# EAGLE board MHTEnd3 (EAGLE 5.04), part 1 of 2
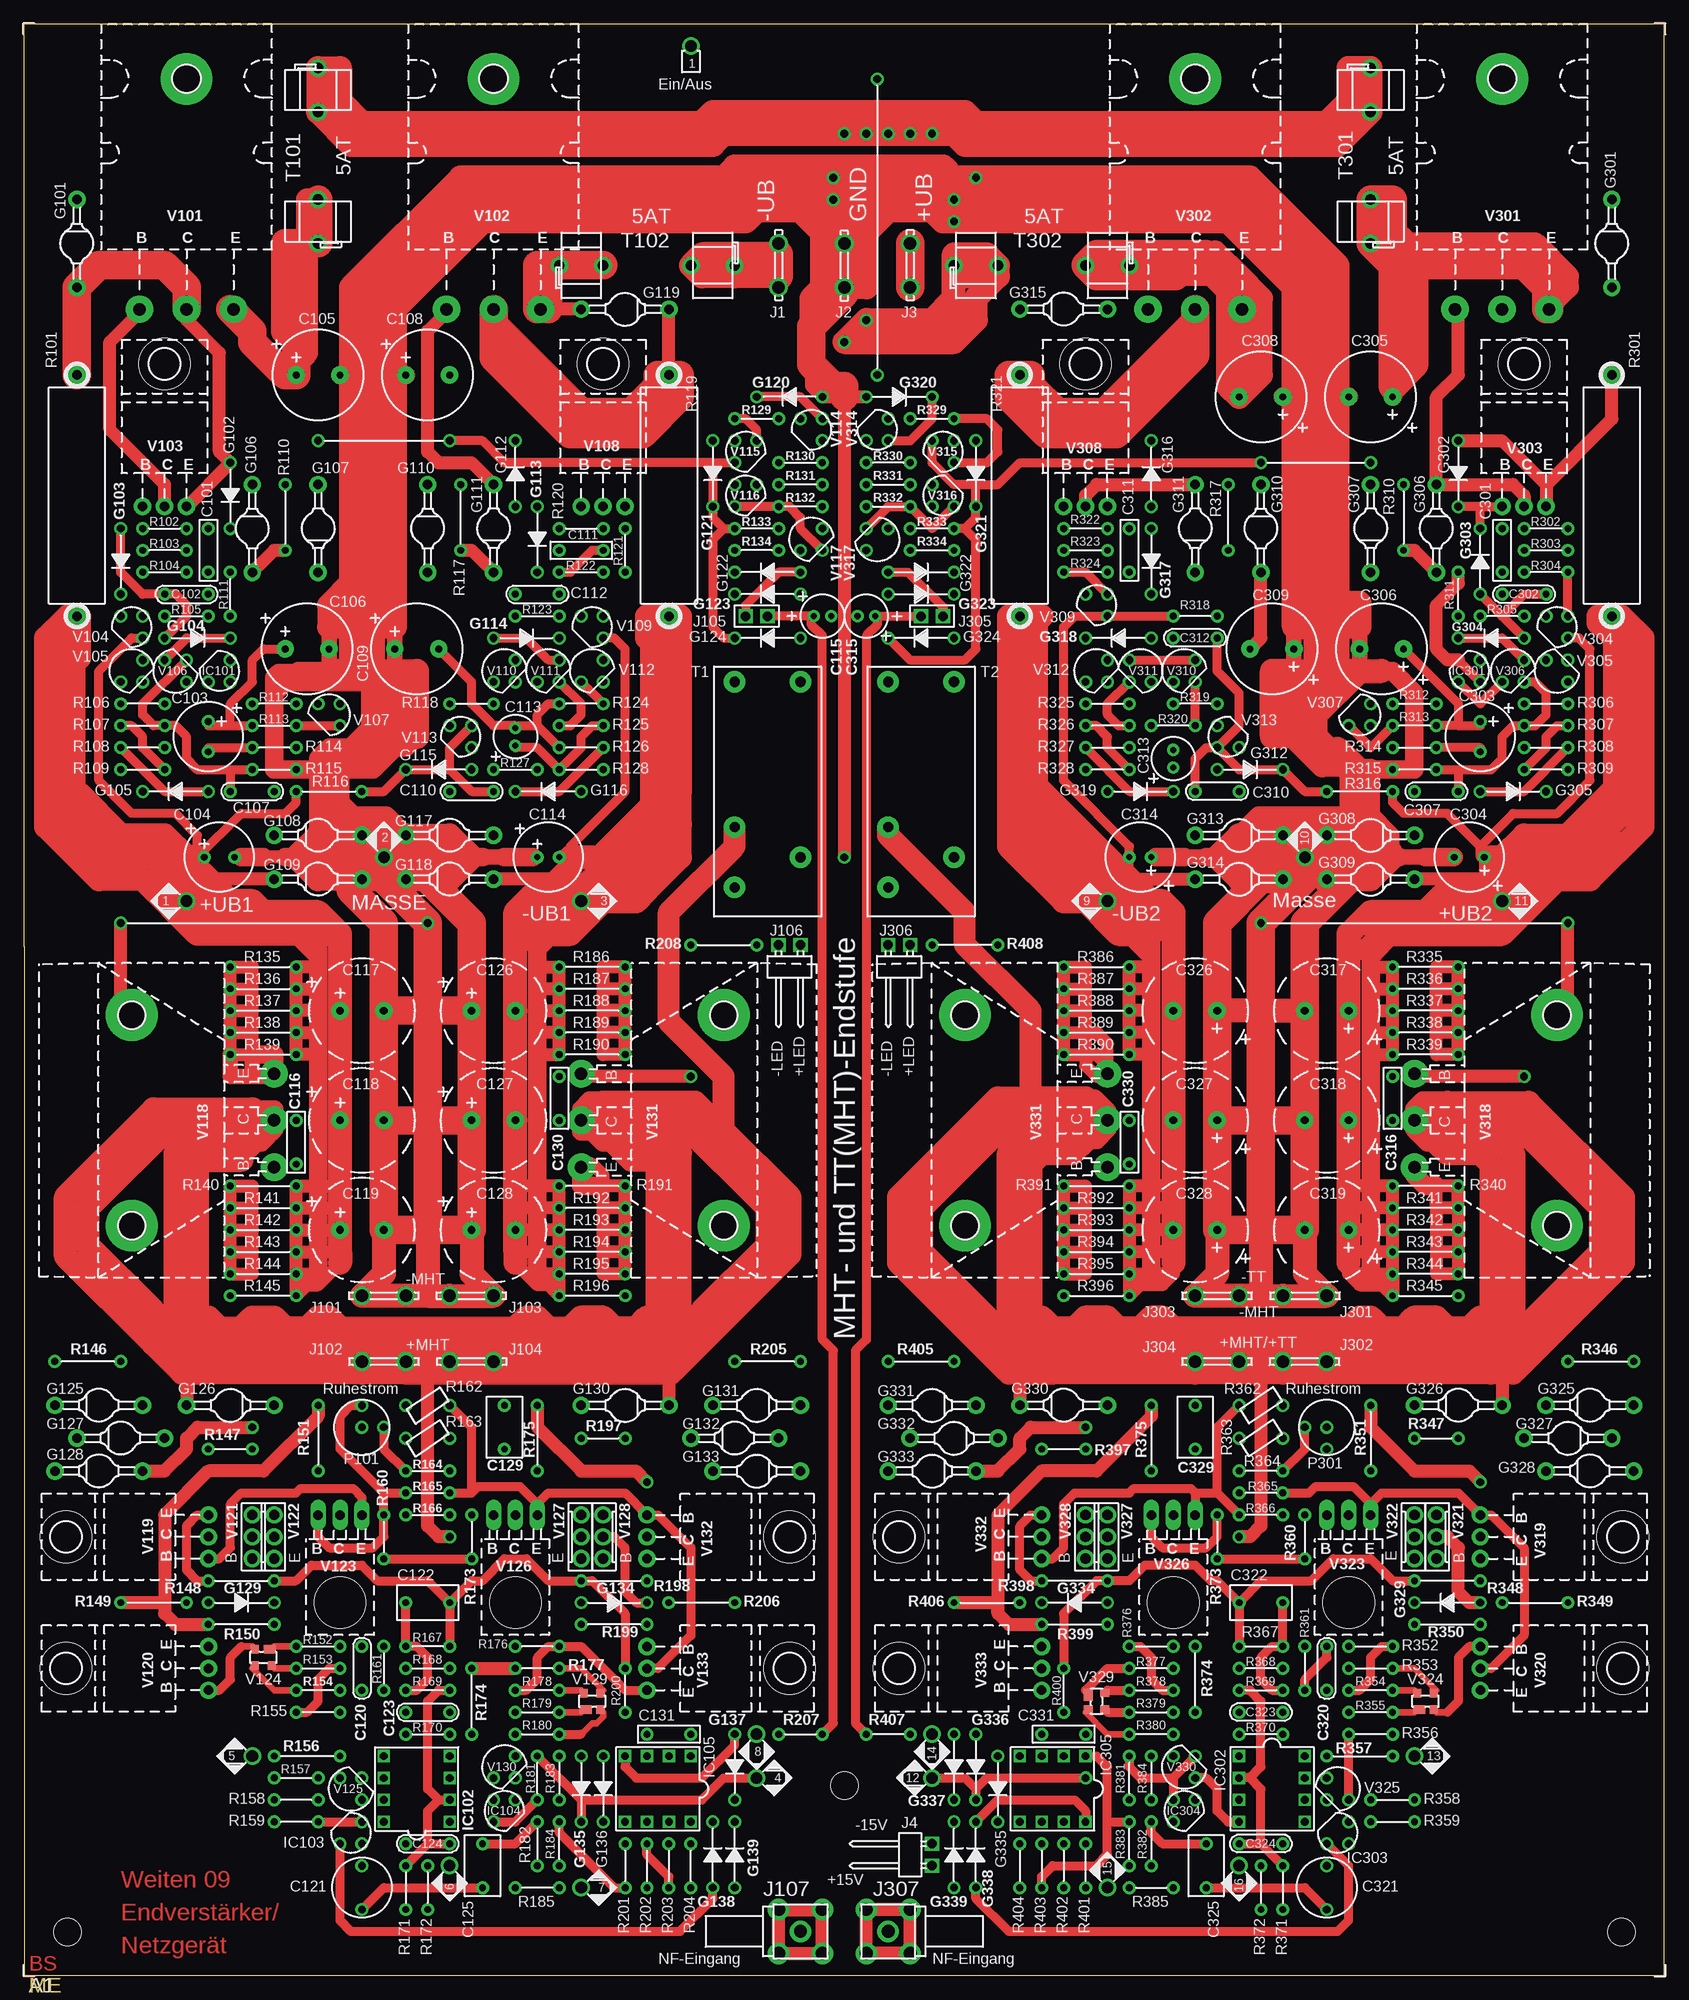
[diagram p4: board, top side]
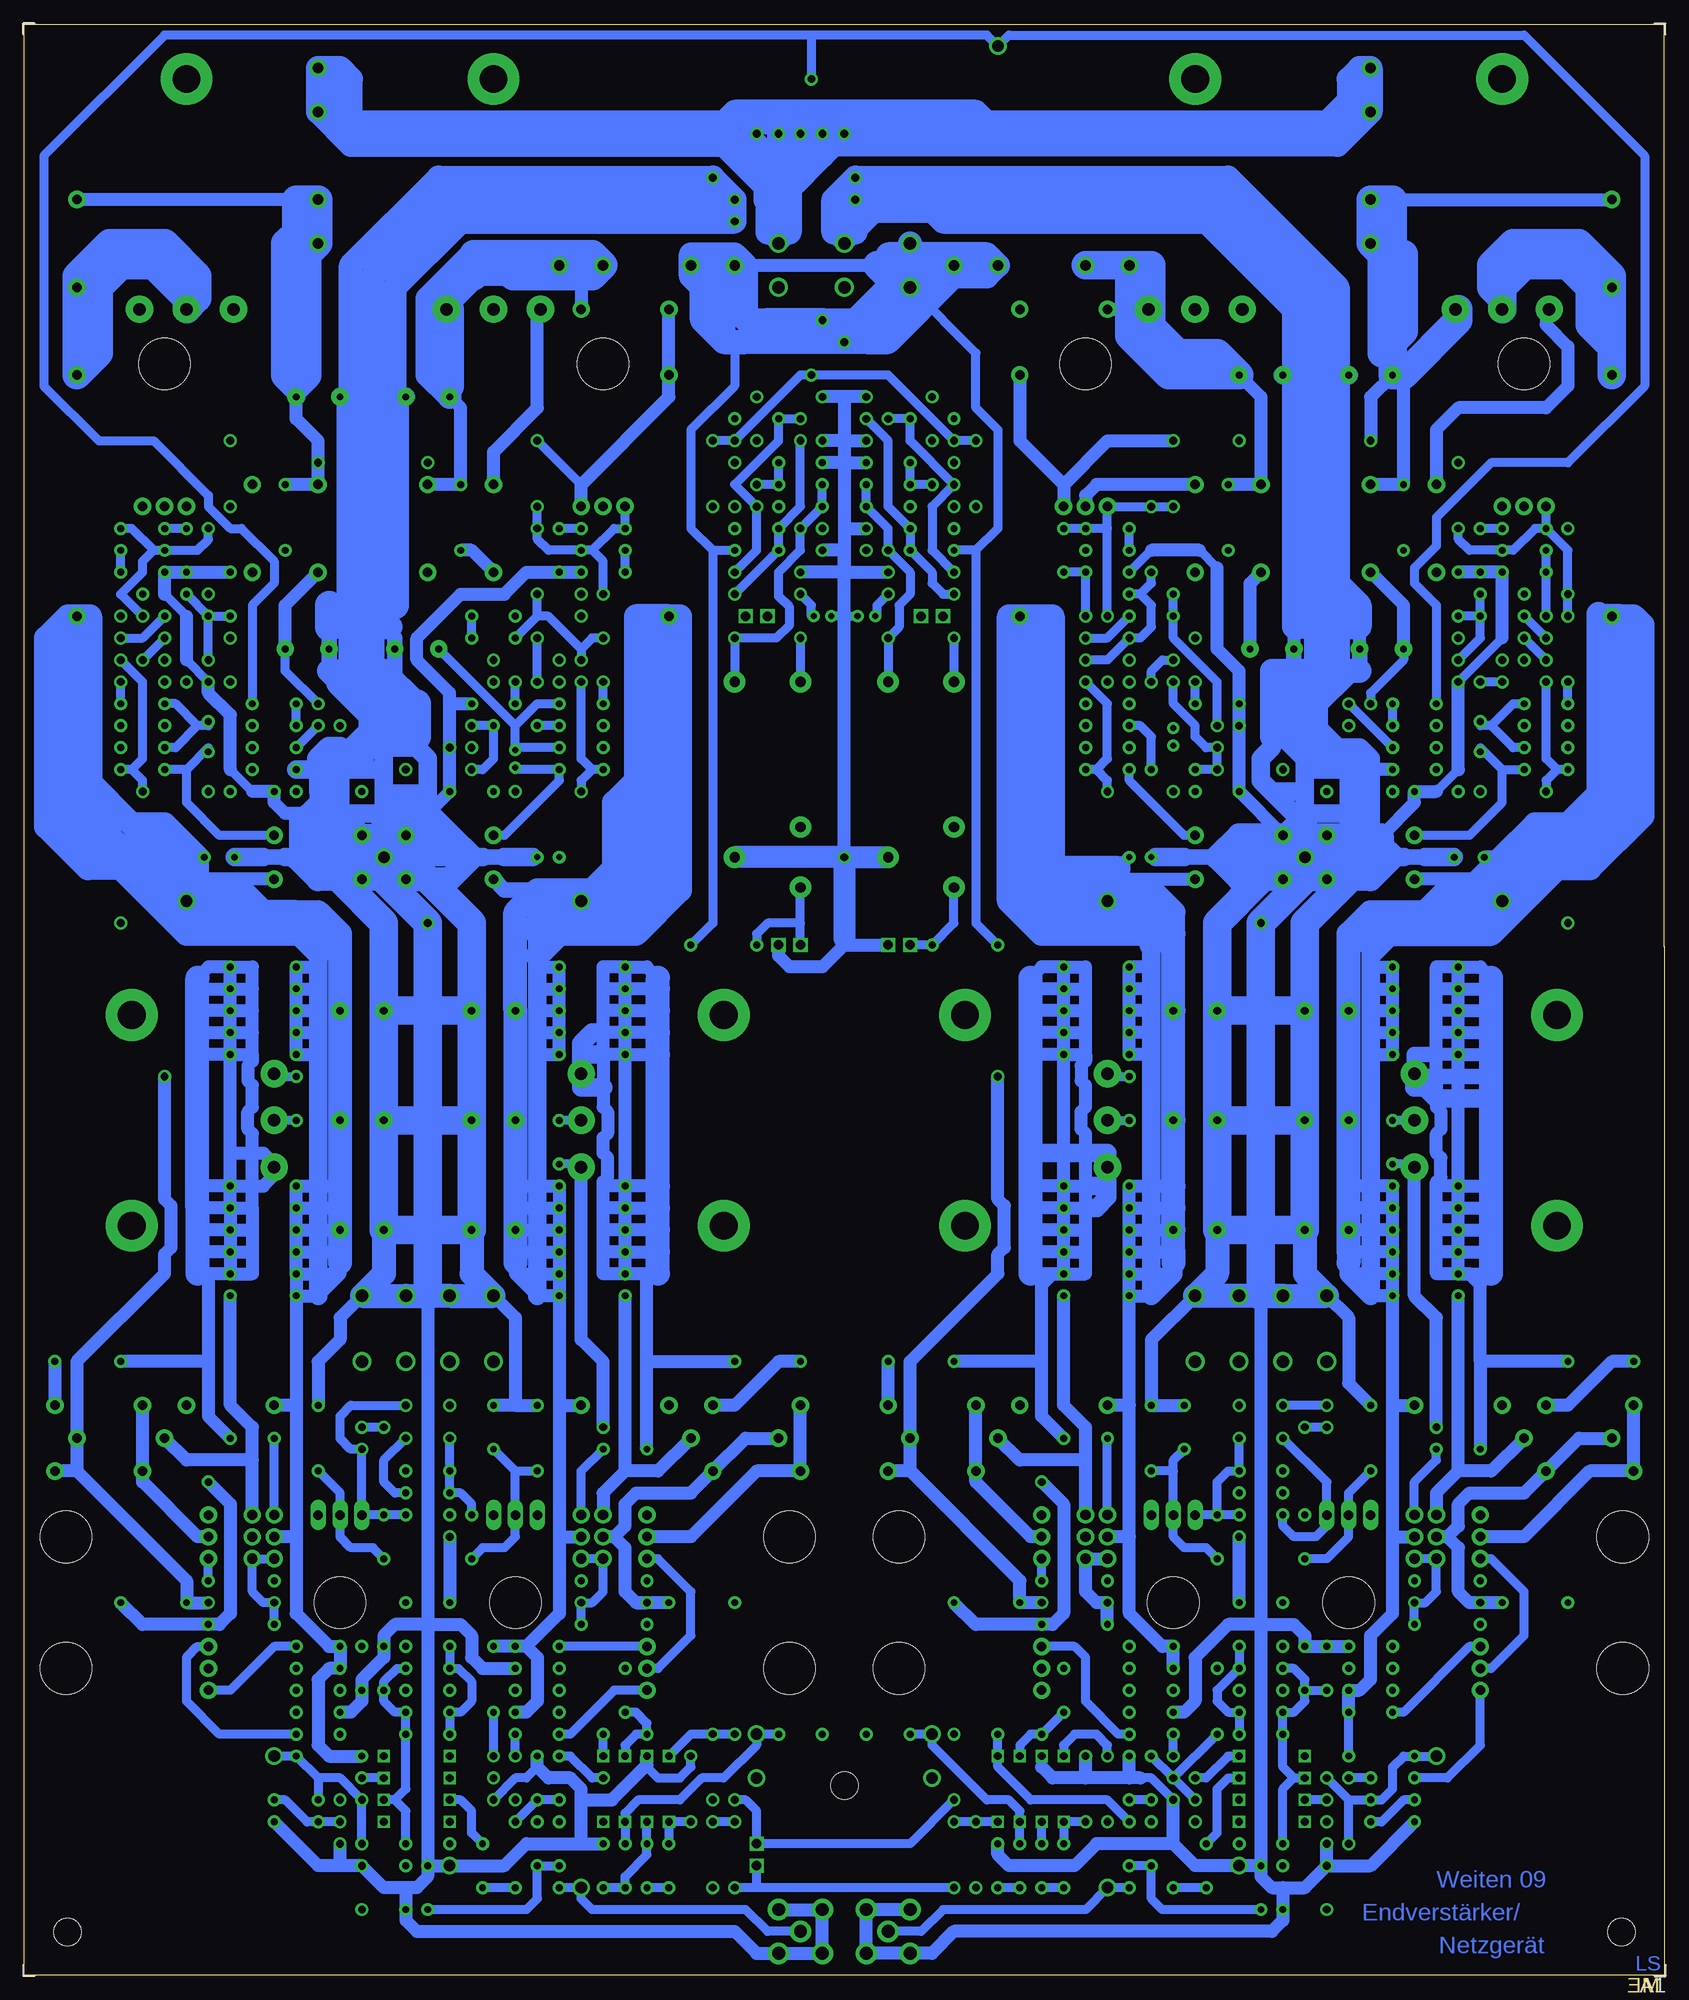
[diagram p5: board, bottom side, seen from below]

Size 190 x 226.06 mm. Coordinates in mm from the lower left corner, seen from the top.
Outline: 190,120 190,0 0,0 0,119.24
Outline: 190,119.38 190,226.06 0,226.06 0,119.13
Copper layers (1*16): Oben/V2 0.035mm / dielectric 1.5mm / Unten/V1 0.035mm
Design rules "default": minimum track width 8mil, minimum drill 24mil, track to track 20mil, track to pad 20mil, pad to pad 20mil, via to via 20mil, smd to smd 20mil, copper to edge 20mil, drill to drill 20mil, minimum pad ring 10mil, minimum via ring 8mil, stop-mask expansion 5mil, vias tented up to drill 0mil, thermal gap 10mil
Holes 6 mm at 185.17,50.8 101.35,50.8 4.83,50.8 88.65,50.8 101.35,35.56 88.65,35.56 185.17,35.56 4.83,35.56 67.06,186.69 16.26,186.69 173.74,186.69 122.94,186.69

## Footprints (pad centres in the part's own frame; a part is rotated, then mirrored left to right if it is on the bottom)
M05T2,5 = drill 0.8 pad 1.499 round: 1 -2.54,0; 2 2.54,0
K5 = drill 0.8 pad 1.499 round: 1 -2.54,0; 2 2.54,0
E3,5S08 = drill 0.8 pad 1.499 round: 1 -1.753,0; 2 1.753,0
E05S10,5 = drill 0.8 pad 2.007 round: 1 -2.54,0; 2 2.54,0
E2,0S05 = drill 0.7 pad 1.397 round: 1 -1.016,0; 2 1.016,0
E2,5S08@1 = drill 0.7 pad 1.499 round: 1 -1.27,0; 2 1.27,0
E05S12,7U = drill 0.9 pad 2.007 round: 1 -2.54,0; 2 2.54,0
KP5/7 = drill 0.9 pad 1.499 round: 1 -2.54,0; 2 2.54,0
M05T4,5 = drill 0.8 pad 1.499 round: 1 -2.54,0; 2 2.54,0
E2,5S08 = drill 0.7 pad 1.499 round: 1 -1.27,0; 2 1.27,0
SOD-57 = drill 1.1 pad 2.007 round: 1 -5.08,0; 2 5.08,0
DIO7-5 = drill 0.9 pad 1.499 round: 1 -2.54,0; 2 5.08,0
TO-92/BC = drill 0.9 pad 1.499 round: 1 1.27,1.27; 2 1.27,-1.27; 3 -1.27,-1.27
DIL-8 = drill 0.9 pad 1.397 square: 1 0,0; 2 2.54,0; 3 5.08,0; 4 7.62,0; 5 7.62,7.62; 6 5.08,7.62; 7 2.54,7.62; 8 0,7.62
FLACH6,3 = drill 1.45 pad 2.184 round: 1 -2.54,0; 2 2.54,0
BERG02SW = drill 1.1 pad 1.499 square: 1 0,0; 2 0,2.54
BERG02SG = drill 1.1 pad 1.499 square: 1 0,0; 2 2.54,0
SMBR665 = drill 1.5 pad 2.489 round: 1 0,0; 2 -2.54,2.54; 3 -2.54,-2.54; 4 2.54,-2.54; 5 2.54,2.54
MESSPU/R = drill 1.35 pad 2.007 round: 1 0,0
T82P = drill 0.9 pad 1.499 round: 1 -2.54,0; 2 0,2.54; S 0,0
R27,5 = drill 1.1 pad 2.007 round: 1 -12.7,0; 2 15.24,0
R5 = drill 0.8 pad 1.499 round: 1 -2.54,0; 2 2.54,0
R7,5 = drill 0.8 pad 1.499 round: 1 -3.81,0; 2 3.81,0
NTC5,0B = drill 0.9 pad 1.499 round: 1 -2.54,0; 2 2.54,0
TYCORT314 = drill 1.2 pad 2.489 round: 11 7.62,2.54; 12 4.12,-5.08; 14 11.12,-5.08; A1 -12.7,-5.08; A2 -12.7,2.54
SICH5*20 = drill 1.2 pad 2.032 round: 1 -10.16,0; 2 -5.08,0; 3 5.08,0; 4 10.16,0
M3 = hole 3.2: 0,0
LÖTFA = drill 1.35 pad 2.032 round: 1 0,0
TO-264/LU = drill 1.45 pad 3.175 round: 1 -5.45,0; 2 0,0; 3 5.43,0
TO-220/LU = drill 1.1 pad 2.007 round: 1 -2.54,0; 2 0,0; 3 2.54,0
TO-92 = drill 0.9 pad 1.499 round: 1 -1.27,-1.27; 2 1.27,-1.27; 3 1.27,1.27
SOT-54 = drill 0.9 pad 1.499 round: B 1.27,-1.27; C 1.27,1.27; E -1.27,1.27
MT200LU = drill 1.45 pad 3.175 round: 1 -5.41,0; 2 0,0; 3 5.41,0
TO-126/S = drill 1.2 pad 2.007 round: 1 -2.54,0; 2 0,0; 3 2.54,0
TO-126/LU = drill 1.1 pad 1.778 long: 1 -2.54,0; 2 0,0; 3 2.54,0 | hole 6: 0,10.16
SOT143 = smd 1.397 x 1.016: 1 0.737,0.965 | smd 0.94 x 1.016: 2 -0.965,0.965; 3 -0.965,-0.94; 4 0.965,-0.94

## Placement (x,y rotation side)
C101  22n/100  [M05T2,5]  21.34,165.1 270 top
C102  12p  [K5]  18.8,160.02 0 top
C103  220µ/25  [E3,5S08]  21.34,143.51 270 top
C104  47µ/63  [E3,5S08]  22.61,129.54 0 top
C105  100µ/63  [E05S10,5]  34.04,185.42 0 top
C106  100µ/63  [E05S10,5]  32.77,153.67 0 top
C107  10n/100  [K5]  26.42,137.16 0 top
C108  100µ/63  [E05S10,5]  46.74,185.42 0 top
C109  100µ/63  [E05S10,5]  45.47,153.67 0 top
C110  1,5n  [K5]  51.82,137.16 0 top
C111  10n/100  [M05T2,5]  64.52,165.1 180 top
C112  12p  [K5]  59.44,160.02 0 top
C113  10µ/100  [E2,0S05]  56.9,143.51 90 top
C114  47µ/63  [E2,5S08@1]  60.71,129.54 0 top
C115  10µ/100  [E2,0S05]  92.46,157.48 0 top
C116  0p  [M05T2,5]  31.5,96.52 90 top
C117  470µ/63  [E05S12,7U]  39.12,111.76 0 top
C118  470µ/63  [E05S12,7U]  39.12,99.06 0 top
C119  470µ/63  [E05S12,7U]  39.12,86.36 0 top
C120  1,5n  [K5]  39.12,35.56 270 top
C121  270p  [KP5/7]  39.12,10.16 90 top
C122  33n/100  [M05T4,5]  46.74,43.18 180 top
C123  82p  [K5]  46.74,30.48 0 top
C124  27p  [K5]  46.74,15.24 0 top
C125  22n/100  [M05T4,5]  53.09,12.7 90 top
C126  470µ/63  [E05S12,7U]  54.36,111.76 0 top
C127  470µ/63  [E05S12,7U]  54.36,99.06 0 top
C128  470µ/63  [E05S12,7U]  54.36,86.36 0 top
C129  220p/250  [M05T4,5]  55.63,63.5 270 top
C130  470p/100  [M05T2,5]  61.98,101.6 90 top
C131  220n/63  [M05T2,5]  74.68,27.94 0 top
C301  22n/100  [M05T2,5]  171.2,165.1 270 top
C302  12p  [K5]  173.74,160.02 180 top
C303  220µ/25  [E3,5S08]  168.66,143.51 270 top
C304  47µ/63  [E3,5S08]  167.39,129.54 180 top
C305  100µ/63  [E05S10,5]  155.96,182.88 180 top
C306  100µ/63  [E05S10,5]  157.23,153.67 180 top
C307  10n/100  [K5]  163.58,137.16 180 top
C308  100µ/63  [E05S10,5]  143.26,182.88 180 top
C309  100µ/63  [E05S10,5]  144.53,153.67 180 top
C310  1,5n  [K5]  138.18,137.16 180 top
C311  10n/100  [M05T2,5]  128.02,165.1 90 top
C312  12p  [K5]  135.64,154.94 180 top
C313  10µ/100  [E2,0S05]  133.1,140.97 90 top
C314  47µ/63  [E2,5S08]  129.29,129.54 180 top
C315  10µ/100  [E2,0S05]  97.54,157.48 180 top
C316  0p  [M05T2,5]  158.5,101.6 270 top
C317  470µ/63  [E05S12,7U]  150.88,111.76 180 top
C318  470µ/63  [E05S12,7U]  150.88,99.06 180 top
C319  470µ/63  [E05S12,7U]  150.88,86.36 180 top
C320  1,5n  [K5]  150.88,35.56 90 top
C321  270p  [KP5/7]  150.88,10.16 90 top
C322  33n/100  [M05T4,5]  143.26,43.18 0 top
C323  82p  [K5]  143.26,30.48 180 top
C324  27p  [K5]  143.26,15.24 180 top
C325  22n/100  [M05T4,5]  136.91,12.7 90 top
C326  470µ/63  [E05S12,7U]  135.64,111.76 180 top
C327  470µ/63  [E05S12,7U]  135.64,99.06 180 top
C328  470µ/63  [E05S12,7U]  135.64,86.36 180 top
C329  220p/250  [M05T4,5]  135.64,63.5 270 top
C330  470p/100  [M05T2,5]  128.02,96.52 270 top
C331  220n/63  [M05T2,5]  120.4,27.94 0 top
G101  BYV27  [SOD-57]  6.1,200.66 90 top
G102  1N4148  [DIO7-5]  23.88,172.72 270 top
G103  1N4148  [DIO7-5]  11.18,165.1 270 top
G104  1N4148  [DIO7-5]  18.8,154.94 0 top
G105  1N4148  [DIO7-5]  18.8,137.16 180 top
G106  BYV27  [SOD-57]  26.42,167.64 90 top
G107  BYV27  [SOD-57]  34.04,167.64 270 top
G108  BYV27  [SOD-57]  34.04,132.08 180 top
G109  BYV27  [SOD-57]  34.04,127 180 top
G110  BYV27  [SOD-57]  46.74,167.64 90 top
G111  BYV27  [SOD-57]  54.36,167.64 270 top
G112  1N4148  [DIO7-5]  56.9,172.72 90 top
G113  1N4148  [DIO7-5]  59.44,167.64 270 top
G114  1N4148  [DIO7-5]  56.9,154.94 0 top
G115  1N4148  [DIO7-5]  49.28,139.7 180 top
G116  1N4148  [DIO7-5]  61.98,137.16 180 top
G117  BYV27  [SOD-57]  49.28,132.08 180 top
G118  BYV27  [SOD-57]  49.28,127 180 top
G119  BYV27  [SOD-57]  69.6,193.04 0 top
G120  1N4148  [DIO7-5]  89.92,182.88 180 top
G121  1N4148  [DIO7-5]  79.76,175.26 270 top
G122  1N4148  [DIO7-5]  87.38,162.56 180 top
G123  1N4148  [DIO7-5]  87.38,160.02 180 top
G124  1N4148  [DIO7-5]  87.38,154.94 180 top
G125  BYV27  [SOD-57]  8.64,66.04 180 top
G126  BYV27  [SOD-57]  23.88,66.04 0 top
G127  BYV27  [SOD-57]  11.18,62.23 180 top
G128  BYV27  [SOD-57]  8.64,58.42 180 top
G129  BAT41  [DIO7-5]  23.88,43.18 0 top
G130  BYV27  [SOD-57]  69.6,66.04 0 top
G131  BYV27  [SOD-57]  84.84,66.04 0 top
G132  BYV27  [SOD-57]  82.3,62.23 180 top
G133  BYV27  [SOD-57]  84.84,58.42 0 top
G134  BAT41  [DIO7-5]  67.06,43.18 0 top
G135  1N4148  [DIO7-5]  64.52,22.86 270 top
G136  1N4148  [DIO7-5]  67.06,22.86 270 top
G137  1N4148  [DIO7-5]  82.3,25.4 270 top
G138  1N4148  [DIO7-5]  79.76,12.7 90 top
G139  1N4148  [DIO7-5]  82.3,12.7 90 top
G301  BYV27  [SOD-57]  183.9,200.66 90 top
G302  1N4148  [DIO7-5]  166.12,175.26 270 top
G303  1N4148  [DIO7-5]  168.66,162.56 90 top
G304  1N4148  [DIO7-5]  171.2,154.94 180 top
G305  1N4148  [DIO7-5]  171.2,137.16 0 top
G306  BYV27  [SOD-57]  163.58,167.64 90 top
G307  BYV27  [SOD-57]  155.96,167.64 270 top
G308  BYV27  [SOD-57]  155.96,132.08 0 top
G309  BYV27  [SOD-57]  155.96,127 0 top
G310  BYV27  [SOD-57]  143.26,167.64 90 top
G311  BYV27  [SOD-57]  135.64,167.64 270 top
G312  1N4148  [DIO7-5]  140.72,139.7 0 top
G313  BYV27  [SOD-57]  140.72,132.08 0 top
G314  BYV27  [SOD-57]  140.72,127 0 top
G315  BYV27  [SOD-57]  120.4,193.04 180 top
G316  1N4148  [DIO7-5]  130.56,172.72 90 top
G317  1N4148  [DIO7-5]  130.56,165.1 270 top
G318  1N4148  [DIO7-5]  128.02,154.94 180 top
G319  1N4148  [DIO7-5]  128.02,137.16 0 top
G320  1N4148  [DIO7-5]  100.08,182.88 0 top
G321  1N4148  [DIO7-5]  110.24,175.26 270 top
G322  1N4148  [DIO7-5]  102.62,162.56 0 top
G323  1N4148  [DIO7-5]  102.62,160.02 0 top
G324  1N4148  [DIO7-5]  105.16,154.94 180 top
G325  BYV27  [SOD-57]  181.36,66.04 180 top
G326  BYV27  [SOD-57]  166.12,66.04 180 top
G327  BYV27  [SOD-57]  178.82,62.23 0 top
G328  BYV27  [SOD-57]  181.36,58.42 180 top
G329  BAT41  [DIO7-5]  166.12,43.18 180 top
G330  BYV27  [SOD-57]  120.4,66.04 180 top
G331  BYV27  [SOD-57]  105.16,66.04 0 top
G332  BYV27  [SOD-57]  107.7,62.23 0 top
G333  BYV27  [SOD-57]  105.16,58.42 0 top
G334  BAT41  [DIO7-5]  122.94,43.18 180 top
G335  1N4148  [DIO7-5]  112.78,22.86 270 top
G336  1N4148  [DIO7-5]  110.24,25.4 270 top
G337  1N4148  [DIO7-5]  107.7,25.4 270 top
G338  1N4148  [DIO7-5]  110.24,12.7 90 top
G339  1N4148  [DIO7-5]  107.7,12.7 90 top
IC101  TL431  [TO-92/BC]  22.61,151.13 0 top
IC102  OPA134  [DIL-8]  49.28,17.78 90 top
IC103  TL431  [TO-92/BC]  37.85,16.51 0 top
IC104  TL431  [TO-92/BC]  55.63,19.05 180 top
IC105  TL062  [DIL-8]  77.22,25.4 180 top
IC301  TL431  [TO-92/BC]  167.39,151.13 0 top
IC302  OPA134  [DIL-8]  140.72,25.4 270 top
IC303  TL431  [TO-92/BC]  152.15,16.51 0 top
IC304  TL431  [TO-92/BC]  134.37,19.05 180 top
IC305  TL062  [DIL-8]  122.94,25.4 180 top
J1  FLACH6,3  [FLACH6,3]  87.38,198.12 270 top
J2  FLACH6,3  [FLACH6,3]  95,198.12 90 top
J3  FLACH6,3  [FLACH6,3]  102.62,198.12 270 top
J4  BERG02SW  [BERG02SW]  105.16,12.7 0 top
J101  FLACH6,3  [FLACH6,3]  41.66,78.74 0 top
J102  FLACH6,3  [FLACH6,3]  41.66,71.12 180 top
J103  FLACH6,3  [FLACH6,3]  51.82,78.74 0 top
J104  FLACH6,3  [FLACH6,3]  51.82,71.12 180 top
J105  BERG02SG  [BERG02SG]  86.11,157.48 180 top
J106  BERG02SW  [BERG02SW]  89.92,119.38 90 top
J107  SMB  [SMBR665]  89.92,5.08 180 top
J301  FLACH6,3  [FLACH6,3]  148.34,78.74 180 top
J302  FLACH6,3  [FLACH6,3]  148.34,71.12 0 top
J303  FLACH6,3  [FLACH6,3]  138.18,78.74 0 top
J304  FLACH6,3  [FLACH6,3]  138.18,71.12 0 top
J305  BERG02SG  [BERG02SG]  103.89,157.48 0 top
J306  BERG02SW  [BERG02SW]  102.62,119.38 90 top
J307  SMB  [SMBR665]  100.08,5.08 0 top
MP1  1  [MESSPU/R]  18.8,124.46 0 top
MP2  3  [MESSPU/R]  64.52,124.46 180 top
MP3  2  [MESSPU/R]  41.66,129.54 270 top
MP4  9  [MESSPU/R]  125.48,124.46 0 top
MP5  10  [MESSPU/R]  148.34,129.54 270 top
MP6  11  [MESSPU/R]  171.2,124.46 180 top
MP7  7  [MESSPU/R]  64.52,10.16 180 top
MP8  15  [MESSPU/R]  125.48,10.16 270 top
MP9  13  [MESSPU/R]  161.04,25.4 180 top
MP10  12  [MESSPU/R]  105.16,22.86 0 top
MP11  5  [MESSPU/R]  26.42,25.4 0 top
MP12  4  [MESSPU/R]  84.84,22.86 180 top
MP13  6  [MESSPU/R]  49.28,12.7 90 top
MP14  16  [MESSPU/R]  140.72,12.7 90 top
MP15  8  [MESSPU/R]  84.84,27.94 90 top
MP16  14  [MESSPU/R]  105.16,27.94 90 top
P101  500  [T82P]  39.12,63.5 270 top
P301  500  [T82P]  150.88,63.5 90 top
R101  0,1  [R27,5]  6.1,172.72 270 top
R102  220  [R5]  16.26,167.64 0 top
R103  430  [R5]  16.26,165.1 180 top
R104  18k  [R5]  16.26,162.56 0 top
R105  39k  [R5]  18.8,157.48 0 top
R106  100  [R5]  13.72,147.32 180 top
R107  33k  [R5]  13.72,144.78 0 top
R108  510  [R5]  13.72,142.24 180 top
R109  8,2k  [R5]  13.72,139.7 0 top
R110  100  [R7,5]  30.23,168.91 270 top
R111  2,7k  [R5]  23.88,160.02 90 top
R112  47k  [R5]  28.96,147.32 180 top
R113  22k  [R5]  28.96,144.78 0 top
R114  100  [R5]  28.96,142.24 180 top
R115  4,7k  [R5]  28.96,139.7 0 top
R116  33k  [R7,5]  35.31,137.16 0 top
R117  100  [R7,5]  50.55,168.91 90 top
R118  2,2  [R5]  51.82,147.32 0 top
R119  0,1  [R27,5]  74.68,170.18 90 top
R120  1k  [R5]  64.52,167.64 0 top
R121  430  [R5]  69.6,165.1 90 top
R122  18k  [R5]  64.52,162.56 0 top
R123  33k  [R5]  59.44,157.48 0 top
R124  100  [R5]  64.52,147.32 180 top
R125  33k  [R5]  64.52,144.78 0 top
R126  510  [R5]  64.52,142.24 180 top
R127  3,9k  [R5]  56.9,139.7 0 top
R128  8,2k  [R5]  64.52,139.7 0 top
R129  1,2M  [R5]  84.84,180.34 0 top
R130  1k  [R5]  89.92,175.26 0 top
R131  47k  [R5]  89.92,172.72 180 top
R132  22k  [R5]  89.92,170.18 180 top
R133  1,2M  [R5]  84.84,167.64 180 top
R134  470K  [R5]  84.84,165.1 180 top
R135  2,2  [R7,5]  27.69,116.84 0 top
R136  2,2  [R7,5]  27.69,114.3 0 top
R137  2,2  [R7,5]  27.69,111.76 0 top
R138  2,2  [R7,5]  27.69,109.22 0 top
R139  2,2  [R7,5]  27.69,106.68 0 top
R140  2,2  [R7,5]  27.69,91.44 0 top
R141  2,2  [R7,5]  27.69,88.9 0 top
R142  2,2  [R7,5]  27.69,86.36 0 top
R143  2,2  [R7,5]  27.69,83.82 0 top
R144  2,2  [R7,5]  27.69,81.28 0 top
R145  15  [R7,5]  27.69,78.74 180 top
R146  33  [R7,5]  7.37,71.12 180 top
R147  100  [R5]  23.88,60.96 180 top
R148  1  [R7,5]  25.15,45.72 0 top
R149  18k  [R7,5]  14.99,43.18 180 top
R150  12k  [R7,5]  25.15,40.64 180 top
R151  5,6k  [R7,5]  34.04,62.23 270 top
R152  33k  [R5]  34.04,38.1 0 top
R153  100  [R5]  34.04,35.56 0 top
R154  120  [R5]  34.04,33.02 180 top
R155  33  [R5]  34.04,30.48 180 top
R156  6,8k  [R7,5]  32.77,25.4 180 top
R157  330  [R5]  31.5,22.86 0 top
R158  12k  [R5]  31.5,20.32 180 top
R159  2,7k  [R5]  31.5,17.78 180 top
R160  680  [R5]  41.66,50.8 270 top
R161  1k  [R5]  41.66,35.56 270 top
R162  3,3k  [NTC5,0B]  46.74,66.04 0 top
R163  3,3k  [NTC5,0B]  46.74,62.23 0 top
R164  100  [R5]  46.74,58.42 0 top
R165  1,5k  [R5]  46.74,55.88 0 top
R166  1,5k  [R5]  46.74,53.34 0 top
R167  150k  [R5]  46.74,38.1 180 top
R168  8,2k  [R5]  46.74,35.56 0 top
R169  47k  [R5]  46.74,33.02 180 top
R170  7,5k  [R5]  46.74,27.94 0 top
R171  2,2k  [R5]  44.2,10.16 270 top
R172  1,5k  [R5]  46.74,10.16 270 top
R173  680  [R5]  51.82,50.8 270 top
R174  6,8k  [R7,5]  51.82,31.75 90 top
R175  5,6k  [R7,5]  59.44,62.23 270 top
R176  33  [R5]  59.44,38.1 180 top
R177  120  [R5]  59.44,35.56 180 top
R178  100  [R5]  59.44,33.02 180 top
R179  33k  [R5]  59.44,30.48 0 top
R180  330  [R5]  59.44,27.94 0 top
R181  2,7k  [R5]  59.44,22.86 90 top
R182  47k  [R5]  59.44,15.24 270 top
R183  12k  [R5]  61.98,22.86 270 top
R184  220k  [R5]  61.98,15.24 90 top
R185  2,2k  [R5]  59.44,10.16 180 top
R186  2,2  [R7,5]  65.79,116.84 180 top
R187  2,2  [R7,5]  65.79,114.3 180 top
R188  2,2  [R7,5]  65.79,111.76 180 top
R189  2,2  [R7,5]  65.79,109.22 180 top
R190  2,2  [R7,5]  65.79,106.68 180 top
R191  2,2  [R7,5]  65.79,91.44 180 top
R192  2,2  [R7,5]  65.79,88.9 180 top
R193  2,2  [R7,5]  65.79,86.36 180 top
R194  2,2  [R7,5]  65.79,83.82 180 top
R195  2,2  [R7,5]  65.79,81.28 180 top
R196  15  [R7,5]  65.79,78.74 180 top
R197  100  [R5]  67.06,62.23 0 top
R198  1  [R7,5]  68.33,45.72 0 top
R199  12k  [R7,5]  68.33,40.64 180 top
R200  1M  [R5]  69.6,33.02 90 top
R201  220k  [R5]  69.6,12.7 270 top
R202  220k  [R5]  72.14,12.7 270 top
R203  220k  [R5]  74.68,12.7 270 top
R204  1M  [R5]  77.22,12.7 90 top
R205  33  [R7,5]  86.11,71.12 180 top
R206  18k  [R7,5]  78.49,43.18 180 top
R207  100k  [R5]  89.92,27.94 0 top
R208  15k  [R7,5]  81.03,119.38 0 top
R301  0,1  [R27,5]  183.9,172.72 270 top
R302  220  [R5]  176.28,167.64 180 top
R303  430  [R5]  176.28,165.1 0 top
R304  18k  [R5]  176.28,162.56 180 top
R305  39k  [R5]  171.2,157.48 180 top
R306  100  [R5]  176.28,147.32 0 top
R307  33k  [R5]  176.28,144.78 180 top
R308  510  [R5]  176.28,142.24 0 top
R309  8,2k  [R5]  176.28,139.7 180 top
R310  10  [R7,5]  159.77,168.91 270 top
R311  2,7k  [R5]  166.12,160.02 90 top
R312  47k  [R5]  161.04,147.32 0 top
R313  22k  [R5]  161.04,144.78 180 top
R314  100  [R5]  161.04,142.24 0 top
R315  4,7k  [R5]  161.04,139.7 180 top
R316  33k  [R7,5]  154.69,137.16 180 top
R317  100  [R7,5]  139.45,168.91 90 top
R318  33k  [R5]  135.64,157.48 180 top
R319  2,2  [R5]  135.64,147.32 180 top
R320  3,9k  [R5]  133.1,144.78 180 top
R321  0,1  [R27,5]  115.32,170.18 90 top
R322  1k  [R5]  122.94,167.64 180 top
R323  430  [R5]  122.94,165.1 0 top
R324  18k  [R5]  122.94,162.56 180 top
R325  100  [R5]  125.48,147.32 0 top
R326  33k  [R5]  125.48,144.78 180 top
R327  510  [R5]  125.48,142.24 0 top
R328  8,2k  [R5]  125.48,139.7 180 top
R329  1,2M  [R5]  105.16,180.34 0 top
R330  1k  [R5]  100.08,175.26 180 top
R331  47k  [R5]  100.08,172.72 0 top
R332  22k  [R5]  100.08,170.18 0 top
R333  1,2M  [R5]  105.16,167.64 180 top
R334  470k  [R5]  105.16,165.1 0 top
R335  2,2  [R7,5]  162.31,116.84 180 top
R336  2,2  [R7,5]  162.31,114.3 180 top
R337  2,2  [R7,5]  162.31,111.76 180 top
R338  2,2  [R7,5]  162.31,109.22 180 top
R339  2,2  [R7,5]  162.31,106.68 180 top
R340  2,2  [R7,5]  162.31,91.44 180 top
R341  2,2  [R7,5]  162.31,88.9 180 top
R342  2,2  [R7,5]  162.31,86.36 180 top
R343  2,2  [R7,5]  162.31,83.82 180 top
R344  2,2  [R7,5]  162.31,81.28 180 top
R345  15  [R7,5]  162.31,78.74 0 top
R346  33  [R7,5]  182.63,71.12 0 top
R347  100  [R5]  163.58,62.23 0 top
R348  1  [R7,5]  164.85,45.72 180 top
R349  18k  [R7,5]  175.01,43.18 0 top
R350  12k  [R7,5]  164.85,40.64 0 top
R351  5,6k  [R7,5]  155.96,62.23 270 top
R352  33  [R5]  155.96,38.1 0 top
R353  120  [R5]  155.96,35.56 0 top
R354  100  [R5]  155.96,33.02 180 top
R355  33k  [R5]  155.96,30.48 180 top
R356  330  [R5]  155.96,27.94 180 top
R357  6,8k  [R7,5]  154.69,25.4 0 top
R358  12k  [R5]  158.5,20.32 0 top
R359  2,7k  [R5]  158.5,17.78 0 top
R360  680  [R5]  148.34,50.8 270 top
R361  1k  [R5]  148.34,35.56 270 top
R362  3,3k  [NTC5,0B]  143.26,66.04 180 top
R363  3,3k  [NTC5,0B]  143.26,62.23 180 top
R364  100  [R5]  143.26,58.42 180 top
R365  1,5k  [R5]  143.26,55.88 180 top
R366  1,5k  [R5]  143.26,53.34 180 top
R367  150k  [R5]  143.26,38.1 0 top
R368  8,2k  [R5]  143.26,35.56 180 top
R369  47k  [R5]  143.26,33.02 0 top
R370  7,5k  [R5]  143.26,27.94 180 top
R371  2,2k  [R5]  145.8,10.16 270 top
R372  1,5k  [R5]  143.26,10.16 270 top
R373  680  [R5]  138.18,50.8 270 top
R374  6,8k  [R7,5]  135.64,34.29 90 top
R375  5,6k  [R7,5]  130.56,62.23 270 top
R376  33  [R5]  130.56,38.1 0 top
R377  33k  [R5]  130.56,35.56 180 top
R378  100  [R5]  130.56,33.02 0 top
R379  120  [R5]  130.56,30.48 0 top
R380  330  [R5]  130.56,27.94 180 top
R381  2,7k  [R5]  128.02,22.86 90 top
R382  47k  [R5]  130.56,15.24 270 top
R383  220k  [R5]  128.02,15.24 90 top
R384  12k  [R5]  130.56,22.86 270 top
R385  2,2k  [R5]  130.56,10.16 0 top
R386  2,2  [R7,5]  124.21,116.84 0 top
R387  2,2  [R7,5]  124.21,114.3 0 top
R388  2,2  [R7,5]  124.21,111.76 0 top
R389  2,2  [R7,5]  124.21,109.22 0 top
R390  2,2  [R7,5]  124.21,106.68 0 top
R391  2,2  [R7,5]  124.21,91.44 0 top
R392  2,2  [R7,5]  124.21,88.9 0 top
R393  2,2  [R7,5]  124.21,86.36 0 top
R394  2,2  [R7,5]  124.21,83.82 0 top
R395  2,2  [R7,5]  124.21,81.28 0 top
R396  15  [R7,5]  124.21,78.74 0 top
R397  100  [R5]  120.4,60.96 180 top
R398  1  [R7,5]  121.67,45.72 180 top
R399  12k  [R7,5]  121.67,40.64 0 top
R400  1M  [R5]  120.4,33.02 90 top
R401  1M  [R5]  122.94,12.7 90 top
R402  220k  [R5]  120.4,12.7 270 top
R403  220k  [R5]  117.86,12.7 270 top
R404  220k  [R5]  115.32,12.7 270 top
R405  33  [R7,5]  103.89,71.12 0 top
R406  18k  [R7,5]  111.51,43.18 0 top
R407  100k  [R5]  100.08,27.94 180 top
R408  15k  [R7,5]  108.97,119.38 180 top
T1  TYCORT314  [TYCORT314]  87.38,137.16 270 top
T2  TYCORT314  [TYCORT314]  105.16,137.16 270 top
T101  5AT  [SICH5*20]  34.04,210.82 270 top
T102  5AT  [SICH5*20]  72.14,198.12 180 top
T301  5AT  [SICH5*20]  155.96,210.82 270 top
T302  5AT  [SICH5*20]  117.86,198.12 0 top
U$4  [M3]  185,5 90 bottom
U$35  [M3]  95,22 90 top
U$36  [M3]  5,5 90 top
U$37  [ECKE/A]  190,226.06 180 top
U$38  [ECKE/A]  0,226.06 270 top
U$40  [ECKE/A]  0,0 0 top
U$56  [A/BEZUG]  0.51,0.51 0 top
U$161  [ECKE/A]  190,0 90 top
U$200  1  [LÖTFA]  77.22,223.52 90 top
V101  MJL1302A  [TO-264/LU]  18.8,193.04 0 top
V102  MJL3281A  [TO-264/LU]  54.36,193.04 0 top
V103  MJE15028  [TO-220/LU]  16.26,170.18 0 top
V104  BC549C  [TO-92/BC]  12.45,156.21 90 top
V105  2N5401  [TO-92]  12.45,151.13 0 top
V106  2N5551  [TO-92]  17.53,151.13 90 top
V107  BC369  [SOT-54]  35.31,146.05 0 top
V108  MJE15029  [TO-220/LU]  67.06,170.18 0 top
V109  BC559C  [TO-92/BC]  65.79,156.21 90 top
V110  2N3906  [TO-92]  55.63,151.13 0 top
V111  2N5401  [TO-92]  60.71,151.13 0 top
V112  2N5551  [TO-92]  65.79,151.13 0 top
V113  BC549C  [TO-92/BC]  50.55,143.51 90 top
V114  BC549C  [TO-92/BC]  91.19,179.07 90 top
V115  BC546B  [TO-92/BC]  83.57,176.53 180 top
V116  BC546B  [TO-92/BC]  83.57,171.45 180 top
V117  2N5401  [TO-92]  91.19,166.37 0 top
V118  2SA1215  [MT200LU]  28.96,99.06 90 top
V119  MJE15030  [TO-220/LU]  21.34,50.8 90 top
V120  MJE15031  [TO-220/LU]  21.34,35.56 90 top
V121  BD140  [TO-126/S]  26.42,50.8 270 top
V122  BD139  [TO-126/S]  28.96,50.8 90 top
V123  BD140  [TO-126/LU]  36.58,53.34 180 top
V124  BCV62  [SOT143]  27.69,36.83 0 top
V125  2N5551  [TO-92]  37.85,21.59 90 top
V126  BD139  [TO-126/LU]  56.9,53.34 180 top
V127  BD140  [TO-126/S]  64.52,50.8 90 top
V128  BD139  [TO-126/S]  67.06,50.8 270 top
V129  BCV61  [SOT143]  65.79,31.75 180 top
V130  2N5401  [TO-92]  55.63,24.13 0 top
V131  2SC2921  [MT200LU]  64.52,99.06 270 top
V132  MJE15031  [TO-220/LU]  72.14,50.8 270 top
V133  MJE15030  [TO-220/LU]  72.14,35.56 270 top
V301  MJL1302A  [TO-264/LU]  171.2,193.04 0 top
V302  MJL3281A  [TO-264/LU]  135.64,193.04 0 top
V303  MJE15028  [TO-220/LU]  173.74,170.18 0 top
V304  BC549C  [TO-92/BC]  177.55,156.21 90 top
V305  2N5401  [TO-92]  177.55,151.13 90 top
V306  2N5551  [TO-92]  172.47,151.13 0 top
V307  BC369  [SOT-54]  154.69,146.05 270 top
V308  MJE15029  [TO-220/LU]  122.94,170.18 0 top
V309  BC559C  [TO-92/BC]  124.21,158.75 90 top
V310  2N3906  [TO-92]  134.37,151.13 0 top
V311  2N5401  [TO-92]  129.29,151.13 270 top
V312  2N5551  [TO-92]  124.21,151.13 0 top
V313  BC549C  [TO-92/BC]  139.45,143.51 270 top
V314  BC549C  [TO-92/BC]  98.81,179.07 0 top
V315  BC546B  [TO-92/BC]  106.43,176.53 90 top
V316  BC546B  [TO-92/BC]  106.43,171.45 270 top
V317  2N5401  [TO-92]  98.81,166.37 180 top
V318  2SA1215  [MT200LU]  161.04,99.06 270 top
V319  MJE15030  [TO-220/LU]  168.66,50.8 270 top
V320  MJE15031  [TO-220/LU]  168.66,35.56 270 top
V321  BD140  [TO-126/S]  163.58,50.8 270 top
V322  BD139  [TO-126/S]  161.04,50.8 90 top
V323  BD140  [TO-126/LU]  153.42,53.34 180 top
V324  BCV62  [SOT143]  162.31,31.75 180 top
V325  2N5551  [TO-92]  152.15,21.59 270 top
V326  BD139  [TO-126/LU]  133.1,53.34 180 top
V327  BD140  [TO-126/S]  125.48,50.8 90 top
V328  BD139  [TO-126/S]  122.94,50.8 270 top
V329  BCV61  [SOT143]  124.21,31.75 90 top
V330  2N5401  [TO-92]  134.37,24.13 90 top
V331  2SC2921  [MT200LU]  125.48,99.06 90 top
V332  MJE15031  [TO-220/LU]  117.86,50.8 90 top
V333  MJE15030  [TO-220/LU]  117.86,35.56 90 top

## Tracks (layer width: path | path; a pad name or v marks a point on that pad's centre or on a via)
+UB  (via drill 0.9 pad 1.5)
  Oben/V2 2.794: T301.2 153.42,215.9 153.42,220.98 | 153.42,220.98 T301.1 T301.2 | T101.1 T101.2 | T101.1 T101.2 | T101.2 37.85,212.09 79.76,212.09 81.03,213.36 v95,213.36 v97.54,213.36 v100.08,213.36 | v100.08,213.36 v102.62,213.36 v105.16,213.36 107.7,213.36 108.97,212.09 152.15,212.09 T301.2 | 110.24,214.63 105.16,214.63 103.89,215.9 | 100.08,215.9 v100.08,213.36 | 100.08,215.9 79.76,215.9 78.49,214.63 39.12,214.63 36.58,217.17 36.58,220.98 T101.1 | 100.08,215.9 103.89,215.9 | 103.89,215.9 108.97,215.9 110.24,214.63 | T301.2 152.15,215.9 150.88,214.63 | 110.24,214.63 150.88,214.63 | 150.88,214.63 153.42,217.17 153.42,220.98
  Oben/V2 3.302: J3.1 J3.2
  Unten/V1 2.159: 103.89,204.47 103.89,205.74 | 103.89,201.93 J3.1 101.35,201.93
  Unten/V1 2.794: 153.42,220.98 153.42,215.9 T301.2 | 153.42,220.98 T301.1 T301.2 | T101.1 T101.2 | T101.1 T101.2 | T101.2 37.85,212.09 96.27,212.09 97.54,210.82 | 97.54,210.82 101.35,207.01 101.35,201.93 | 152.15,212.09 108.97,212.09 103.89,207.01 102.62,207.01 102.62,209.55 | 103.89,201.93 103.89,204.47 | T101.1 T101.2 | T101.1 T101.2 | 78.49,214.63 39.12,214.63 36.58,217.17 36.58,219.71 35.31,220.98 T101.1 | 97.54,214.63 78.49,214.63 | 97.54,214.63 98.81,214.63 | 108.97,214.63 107.7,214.63 | 107.7,214.63 102.62,209.55 | 102.62,209.55 100.08,212.09 v100.08,213.36 98.81,214.63 | 98.81,214.63 102.62,214.63 | 102.62,214.63 107.7,214.63 | 108.97,214.63 107.7,215.9 79.76,215.9 78.49,214.63 | 108.97,214.63 152.15,214.63 | 152.15,214.63 152.15,212.09 | 152.15,212.09 T301.2 | 102.62,214.63 102.62,209.55 | 97.54,210.82 97.54,214.63 | 152.15,214.63 152.15,219.71 153.42,220.98
  Unten/V1 3.302: 103.89,207.01 103.89,205.74
+UB0  (via drill 0.9 pad 1.5)
  Oben/V2 2.159: C305.1 158.5,184.15
  Oben/V2 2.54: 176.28,193.04 178.82,195.58 178.82,196.85 175.01,200.66 159.77,200.66
  Oben/V2 3.302: 161.04,198.12 161.04,186.69 158.5,184.15 158.5,198.12 T301.4 T301.3 158.5,205.74 158.5,201.93 159.77,200.66 161.04,199.39 161.04,198.12 | V301.3 176.28,193.04 176.28,195.58 173.74,198.12 161.04,198.12
  Unten/V1 1.524: C305.1 158.5,180.34 155.96,177.8 v155.96,175.26 G307.1 R310.1 | 158.5,205.74 G301.2
  Unten/V1 2.159: C305.1 158.5,184.15
  Unten/V1 3.302: T301.4 T301.3 158.5,205.74 158.5,201.93 159.77,200.66 159.77,185.42 158.5,184.15 157.23,185.42 157.23,199.39 T301.4
+UB1
  Oben/V2 1.016: V104.3 12.45,154.94 8.64,151.13 8.64,138.43 12.45,134.62 17.53,134.62 20.07,132.08 20.07,129.54 25.15,134.62 30.23,134.62 31.5,135.89 R116.1
  Oben/V2 1.524: R136.2 R135.2 34.04,116.84 | R137.2 R136.2 | R138.2 R137.2 | R138.2 R139.2 34.04,106.68 | R141.2 R140.2 36.58,91.44 | R142.2 R141.2 | R143.2 R142.2 | R144.2 R143.2 | R144.2 R145.1 32.77,80.01 34.04,80.01 36.58,82.55 35.31,81.28 34.04,81.28 R144.2 | R141.2 36.58,88.9 | R142.2 C119.1 | C104.1 20.07,129.54 | 6.35,136.91 6.35,152.65 | G109.2 21.34,127 | R143.2 36.58,83.82 | R136.2 34.04,114.3 | 34.04,111.76 R137.2 | R138.2 34.04,109.22
  Oben/V2 2.159: 34.04,81.28 34.04,106.68 34.04,109.22 34.04,111.76 34.04,114.3 34.04,116.84 34.04,118.11 | 34.04,118.11 34.04,120.65 | 34.04,118.11 31.5,120.65
  Oben/V2 2.794: 36.58,82.55 36.58,83.82 C119.1 36.58,88.9 36.58,91.44 C118.1 C117.1 36.58,120.65 | 18.8,129.54 21.34,127 23.88,124.46 26.42,124.46 27.69,123.19 34.04,123.19 36.58,120.65 | 20.07,129.54 18.8,129.54 | 18.8,129.54 16.26,132.08 11.18,132.08 6.35,136.91 | 36.58,120.65 34.04,120.65 31.5,120.65 26.42,120.65 | 26.42,120.65 25.15,121.92 22.61,121.92 14.99,129.54 9.91,129.54 5.08,134.37 5.08,157.48 | 26.42,120.65 20.07,120.65 13.72,127 8.64,127 2.54,133.1 2.54,154.94 5.08,157.48 | 6.35,152.65 6.35,157.48 | R101.2 5.08,157.48
  Unten/V1 1.016: V104.3 R105.1 | R156.1 R155.1
  Unten/V1 1.524: R136.2 R135.2 34.04,116.84 | R137.2 R136.2 | R138.2 R137.2 | R144.2 R143.2 | R143.2 R142.2 | R142.2 R141.2 | R141.2 R140.2 36.58,91.44 | R138.2 R139.2 34.04,106.68 | R145.1 R144.2 | 31.5,66.04 R145.1 | R141.2 36.58,88.9 | R142.2 C119.1 | R145.1 34.04,78.74 | 18.8,129.54 C104.1 | 31.5,50.8 31.5,41.91 34.04,39.37 34.04,34.29 35.31,33.02 R154.1 R155.1 | 31.5,50.8 31.5,66.04 | 31.5,66.04 G126.2 | MP1.1 21.34,127 G109.2 | 31.5,50.8 V122.2 | R143.2 36.58,83.82 | R144.2 36.58,81.28 | 34.04,114.3 R136.2 | 34.04,111.76 R137.2 | 34.04,109.22 R138.2
  Unten/V1 2.159: 36.58,82.55 36.58,81.28 34.04,78.74 34.04,106.68 34.04,109.22 34.04,111.76 34.04,114.3 34.04,116.84 34.04,118.11 | 34.04,118.11 34.04,119.38 | 34.04,118.11 31.5,120.65
  Unten/V1 2.794: 36.58,82.55 36.58,83.82 C119.1 36.58,88.9 36.58,91.44 C118.1 C117.1 36.58,120.65 | 11.18,133.35 7.62,136.91 7.62,157.73 | 36.58,120.65 34.04,123.19 27.69,123.19 | 27.69,123.19 25.15,123.19 22.61,125.73 | 22.61,125.73 21.34,127 18.8,129.54 14.99,133.35 11.18,133.35 | 2.54,138.18 2.54,156.46 3.56,157.48 5.08,157.48 | 12.45,128.27 20.07,120.65 23.88,120.65 | 12.45,128.27 5.08,135.64 | 5.08,135.64 2.54,138.18 | 36.58,120.65 32.77,120.65 | 32.77,120.65 31.5,120.65 23.88,120.65 | 23.88,120.65 11.18,133.35 | 34.04,119.38 32.77,120.65 | 12.45,128.27 8.64,128.27 2.54,134.37 2.54,138.18 | 27.69,123.19 25.15,125.73 22.61,125.73 | 5.08,157.48 R101.2 7.37,157.48 | 5.08,135.64 5.08,157.48
+UB2
  Oben/V2 1.016: V304.3 180.09,154.94 181.36,153.67 181.36,138.43 177.55,134.62 172.47,134.62 168.66,130.81 | R316.1 158.5,135.89 159.77,134.62 164.85,134.62 168.66,130.81 | C304.1 168.66,129.54 168.66,130.81
  Oben/V2 1.524: R336.2 R335.2 155.96,116.84 | R337.2 R336.2 | R338.2 R337.2 | R344.2 R343.2 | R343.2 R342.2 | R342.2 R341.2 | R341.2 R340.2 153.42,91.44 | R338.2 R339.2 155.96,106.68 | R344.2 R345.1 157.23,80.01 154.69,80.01 153.42,81.28 | R341.2 153.42,88.9 | R342.2 C319.1 | R344.2 155.96,81.28 153.42,81.28 | 153.42,81.28 153.42,82.55 | 169.93,129.54 C304.1 | 183.65,133.1 183.65,136.91 183.65,155.19 | 169.93,127 G309.2 | R343.2 153.42,83.82 | 155.96,114.3 R336.2 | 155.96,111.76 R337.2 | 155.96,109.22 R338.2
  Oben/V2 2.159: 155.96,81.28 155.96,106.68 155.96,109.22 155.96,111.76 155.96,114.3 155.96,116.84 155.96,118.87
  Oben/V2 2.54: 183.65,133.1 184.92,134.37 | 184.92,154.18 182.38,156.72
  Oben/V2 2.794: 153.42,82.55 153.42,83.82 C319.1 153.42,88.9 153.42,91.44 C318.1 C317.1 153.42,120.65 154.69,121.92 | 183.65,133.1 180.09,129.54 171.2,129.54 | 184.92,134.37 184.92,154.18 184.92,157.48 187.46,154.94 187.46,133.1 181.36,127 177.55,127 | 171.2,129.54 169.93,129.54 169.93,127 | 171.2,129.54 173.74,132.08 178.82,132.08 183.65,136.91 | 173.74,127 169.93,127 | 173.74,127 177.55,127 | 154.69,121.92 155.96,121.92 | 154.69,121.92 155.96,123.19 162.31,123.19 | 162.31,123.19 166.12,123.19 168.66,125.73 | 169.93,127 168.66,125.73 | 157.74,120.65 167.39,120.65 | 167.39,120.65 173.74,127 | 167.39,120.65 171.2,120.65 177.55,127 | 182.38,156.72 182.38,157.48 | 162.31,123.19 164.85,125.73 168.66,125.73
  Oben/V2 3.302: 155.96,118.87 157.74,120.65
  Unten/V1 1.016: R305.1 176.28,154.94 V304.3
  Unten/V1 1.524: 158.5,66.04 158.5,50.8 | 158.5,50.8 158.5,41.91 154.69,38.1 R352.1 R353.1 154.69,35.56 155.96,34.29 155.96,26.67 154.69,25.4 R357.1 | R345.1 158.5,66.04 | 158.5,66.04 G326.2 | 153.42,91.44 R340.2 R341.2 | R341.2 153.42,88.9 | R342.2 C319.1 | R345.1 155.96,78.74 153.42,81.28 | 153.42,81.28 153.42,82.55 | R336.2 R335.2 155.96,116.84 | R337.2 R336.2 | R338.2 R337.2 | R338.2 R339.2 155.96,106.68 | R342.2 R341.2 | R343.2 R342.2 | R344.2 R343.2 | R344.2 R345.1 | C304.1 169.93,129.54 | G309.2 169.93,127 | 158.5,50.8 V322.2 | R343.2 153.42,83.82 | R344.2 153.42,81.28 | R336.2 155.96,114.3 | R337.2 155.96,111.76 | R338.2 155.96,109.22
  Unten/V1 2.159: 155.96,118.11 155.96,120.65 | 155.96,78.74 155.96,106.68 155.96,109.22 155.96,111.76 155.96,114.3 155.96,116.84 155.96,118.11 | 155.96,118.11 158.5,120.65
  Unten/V1 2.54: 178.82,130.81 180.09,132.08
  Unten/V1 2.794: 153.42,82.55 153.42,83.82 C319.1 153.42,88.9 153.42,91.44 C318.1 C317.1 153.42,118.11 | 184.92,136.91 184.92,157.48 | 180.09,132.08 184.92,136.91 | 175.01,130.81 171.2,130.81 | 177.55,130.81 175.01,130.81 | 177.55,130.81 178.82,130.81 | 171.2,130.81 169.93,129.54 169.93,127 168.66,125.73 | 184.92,136.91 184.92,134.37 178.82,128.27 | 155.96,120.65 153.42,118.11 | 155.96,120.65 158.5,123.19 | 158.5,123.19 162.31,123.19 | 162.31,123.19 166.12,123.19 168.66,125.73 | 155.96,120.65 158.5,120.65 167.39,120.65 | 167.39,120.65 171.2,120.65 178.82,128.27 | 171.2,130.81 173.74,133.35 177.55,133.35 182.38,138.18 182.38,157.48 R301.2 184.92,157.48 | 175.01,130.81 172.47,128.27 172.47,125.73 MP6.1 | 178.82,128.27 182.63,128.27 187.46,133.1 187.46,154.94 184.92,157.48 | 162.31,123.19 164.85,125.73 168.66,125.73 | 158.5,123.19 155.96,123.19 153.42,120.65 153.42,118.11 | 167.39,120.65 MP6.1 | MP6.1 177.55,130.81
-UB  (via drill 0.9 pad 1.5)
  Oben/V2 1.778: 107.7,199.39 T302.1 107.7,196.85
  Oben/V2 2.159: 87.38,199.39 J1.1 | J1.2 87.38,196.85
  Oben/V2 2.794: 112.78,196.85 107.7,196.85 107.7,191.77 105.16,189.23 v95,189.23 | v95,189.23 v97.54,191.77 105.16,191.77 107.7,194.31 107.7,199.39 111.51,199.39 T302.2 112.78,196.85 | 82.3,196.85 78.49,196.85 T102.2 78.49,199.39 87.38,199.39 | 87.38,196.85 82.3,196.85 | 82.3,196.85 T102.1 | 112.78,196.85 110.24,194.31 110.24,191.77 107.7,189.23 v95,189.23
  Oben/V2 3.302: 87.38,196.85 87.38,199.39
  Unten/V1 1.016: J1.2 79.76,187.96 79.76,181.61 77.22,179.07 77.22,167.64 79.76,165.1 | 79.76,165.1 79.76,121.92 R208.1 | 110.24,165.1 112.78,167.64 112.78,179.07 107.7,184.15 107.7,187.96 106.43,189.23 | 110.24,165.1 110.24,121.92 R408.1 | 110.24,165.1 R334.2 | 79.76,165.1 R134.2
  Unten/V1 1.524: 106.43,198.12 91.19,198.12
  Unten/V1 2.794: 82.3,196.85 78.49,196.85 T102.2 78.49,199.39 89.92,199.39 | 82.3,196.85 86.11,196.85 J1.2 87.38,194.31 92.46,189.23 | 108.97,196.85 112.78,196.85 | 108.97,196.85 107.7,196.85 | J1.1 87.38,198.12 93.73,191.77 v97.54,191.77 103.64,191.77 | v95,189.23 108.97,189.23 | 92.46,189.23 89.92,189.23 82.3,196.85 | 92.46,189.23 v95,189.23 | v95,189.23 106.43,189.23 108.97,189.23 | 112.78,196.85 T302.2 112.78,199.39 107.7,199.39 106.43,198.12 106.43,191.77 103.89,191.77 | 108.97,189.23 108.97,196.85 | 108.97,189.23 111.51,191.77 111.51,195.58 112.78,196.85
  Unten/V1 3.302: 89.92,198.12 91.19,198.12 89.92,196.85
-UB0
  Oben/V2 1.524: G119.1 60.71,193.04
  Oben/V2 3.302: 60.71,198.12 T102.3 T102.4 60.71,198.12 | 60.71,198.12 59.44,198.12 59.44,193.04 | 60.71,193.04 60.71,198.12
  Unten/V1 1.524: G119.1 V102.3 | C108.2 46.74,182.88 G110.2 R117.2
  Unten/V1 3.302: 59.44,191.77 59.44,191.01 56.39,187.96 51.82,187.96 C108.2 57.41,185.42 61.98,189.99 61.98,191.77 | 59.44,193.04 59.44,191.77 | 59.44,193.04 59.44,198.12 T102.4 | T102.4 T102.3 63.25,198.12 | 59.44,191.77 61.98,191.77 | T102.4 61.98,191.77 | V102.3 59.44,193.04
-UB1
  Oben/V2 1.016: V109.3 68.33,154.94 69.6,153.67 69.6,137.16 63.25,130.81 63.25,129.54
  Oben/V2 1.524: R187.2 R186.2 59.44,116.84 | R188.2 R187.2 | R189.2 R188.2 | R189.2 R190.2 59.44,106.68 | R192.2 R191.2 56.9,91.44 | R193.2 R192.2 | R194.2 R193.2 | R195.2 R194.2 | R195.2 R196.2 60.71,80.01 59.44,80.01 56.9,82.55 58.17,81.28 59.44,81.28 R195.2 | R193.2 C128.2 | R192.2 56.9,88.9 | 72.14,154.94 72.14,135.89 65.79,129.54 | 63.25,129.54 C114.2 | 61.98,127 G118.1 | R174.2 R177.2 | R194.2 56.9,83.82 | R187.2 59.44,114.3 | 59.44,111.76 R188.2 | R189.2 59.44,109.22
  Oben/V2 2.159: 59.44,119.38 59.44,116.84 59.44,114.3 59.44,111.76 59.44,109.22 59.44,106.68 59.44,81.28
  Oben/V2 2.794: 56.9,82.55 56.9,83.82 C128.2 56.9,88.9 56.9,91.44 C127.2 C126.2 56.9,123.19 59.44,125.73 60.71,125.73 61.98,127 63.25,128.27 63.25,129.54 65.79,129.54 | 73.41,157.48 73.41,134.62 | 72.14,133.35 72.14,125.73 | 65.79,127 61.98,123.19 60.71,123.19 59.44,121.92 59.44,119.38 60.71,120.65 63.25,120.65 67.06,124.46 70.87,124.46 72.14,125.73 | 65.79,127 69.6,127 75.95,133.35 | 75.95,137.16 75.95,157.48 R119.1 73.41,157.48 | 75.95,133.35 75.95,137.16 | 75.95,133.35 75.95,129.54 72.14,125.73 | 72.14,154.94 72.14,157.48 73.41,157.48 | 73.41,134.62 75.95,137.16 | 72.14,133.35 73.41,134.62 | 65.79,127 72.14,133.35
  Unten/V1 1.016: V109.3 64.52,154.94 R123.2
  Unten/V1 1.524: R196.2 R195.2 | R195.2 R194.2 | R194.2 R193.2 | R193.2 R192.2 | R192.2 R191.2 56.9,91.44 | R189.2 R190.2 59.44,106.68 | R189.2 R188.2 | R188.2 R187.2 | R187.2 R186.2 59.44,116.84 | 61.98,66.04 R196.2 | R192.2 56.9,88.9 | R193.2 C128.2 | R196.2 59.44,78.74 | 63.25,128.27 C114.2 | R177.2 R176.2 58.17,38.1 61.98,41.91 61.98,50.8 | 63.25,127 G118.1 | 61.98,50.8 V127.2 | 61.98,50.8 61.98,66.04 | 61.98,66.04 G130.1 | R194.2 56.9,83.82 | R195.2 56.9,81.28 | 59.44,114.3 R187.2 | 59.44,111.76 R188.2 | 59.44,109.22 R189.2
  Unten/V1 2.159: 59.44,119.38 59.44,116.84 59.44,114.3 59.44,111.76 59.44,109.22 59.44,106.68 59.44,78.74 56.9,81.28 56.9,82.55
  Unten/V1 2.794: 56.9,82.55 56.9,83.82 C128.2 56.9,88.9 56.9,91.44 C127.2 C126.2 56.9,120.65 | 59.44,119.38 59.44,121.92 60.71,123.19 63.25,123.19 MP2.1 64.52,123.19 | 70.87,127 69.6,125.73 64.52,125.73 64.52,123.19 | 56.9,120.65 56.9,123.19 59.44,125.73 61.98,125.73 63.25,127 63.25,128.27 70.87,128.27 70.87,157.48 73.41,157.48 | 64.52,123.19 70.87,123.19 73.41,125.73 73.41,157.48 | 56.9,120.65 72.14,120.65 75.95,124.46 75.95,157.48 R119.1 73.41,157.48
-UB2
  Oben/V2 1.016: R318.2 V309.3 121.67,157.48 120.4,156.21 120.4,138.43 128.02,130.81 C314.2 128.02,127
  Oben/V2 1.524: R395.2 R396.2 129.29,80.01 131.83,80.01 133.1,81.28 | R394.2 R395.2 | R393.2 R394.2 | R392.2 R393.2 | R392.2 R391.2 133.1,91.44 | R389.2 R390.2 130.56,106.68 | R389.2 R388.2 | R388.2 R387.2 | R387.2 R386.2 130.56,116.84 | 133.1,81.28 130.56,81.28 R395.2 | C328.2 R393.2 | 133.1,88.9 R392.2 | 133.1,82.55 133.1,81.28 | 117.86,137.16 117.86,157.48 | 128.02,127 G314.1 | 133.1,83.82 R394.2 | 130.56,114.3 R387.2 | 130.56,111.76 R388.2 | 130.56,109.22 R389.2
  Oben/V2 1.778: 126.75,124.46 MP4.1
  Oben/V2 2.159: 130.56,120.65 130.56,118.11 | 130.56,118.11 130.56,116.84 130.56,114.3 130.56,111.76 130.56,109.22 130.56,106.68 130.56,81.28 | 128.02,120.65 130.56,118.11
  Oben/V2 2.794: 133.1,82.55 133.1,83.82 C328.2 133.1,88.9 133.1,91.44 C327.2 C326.2 133.1,123.19 131.83,124.46 130.56,124.46 128.02,127 117.86,137.16 | 116.59,135.89 125.48,127 | 116.59,157.48 R321.1 | 116.59,157.48 116.59,135.89 | 116.59,157.48 117.86,157.48 R321.1 | R321.1 114.05,157.48 114.05,130.81 120.4,124.46 122.94,124.46 | 116.59,135.89 116.59,132.08 122.94,125.73 122.94,124.46 | 124.21,127 126.75,124.46 128.02,123.19 129.29,123.19 130.56,121.92 130.56,120.65 128.02,120.65 126.75,120.65 122.94,124.46
  Unten/V1 1.524: R396.2 128.02,66.04 | 133.1,91.44 R391.2 R392.2 | 133.1,88.9 R392.2 | C328.2 R393.2 | 133.1,82.55 133.1,81.28 | 133.1,81.28 R395.2 | R396.2 130.56,78.74 133.1,81.28 | R387.2 R386.2 130.56,116.84 | R388.2 R387.2 | R389.2 R388.2 | R389.2 R390.2 130.56,106.68 | R392.2 R393.2 | R393.2 R394.2 | R394.2 R395.2 | R395.2 R396.2 | 128.02,66.04 G330.1 | 128.02,66.04 128.02,50.8 | 128.02,50.8 128.02,41.91 131.83,38.1 | 131.83,38.1 130.56,36.83 130.56,31.75 131.83,30.48 R379.2 | 128.02,50.8 V327.2 | 133.1,83.82 R394.2 | 130.56,114.3 R387.2 | 130.56,111.76 R388.2 | 130.56,109.22 R389.2 | 131.83,38.1 R376.2 R374.2
  Unten/V1 1.778: G314.1 134.37,125.73 130.56,125.73
  Unten/V1 2.159: 130.56,78.74 130.56,106.68 130.56,109.22 130.56,111.76 130.56,114.3 130.56,116.84 130.56,118.11 130.56,120.65
  Unten/V1 2.794: 133.1,82.55 133.1,83.82 C328.2 133.1,88.9 133.1,91.44 C327.2 C326.2 133.1,123.19 130.56,125.73 124.21,125.73 | 116.59,157.48 116.59,137.16 | 121.67,125.73 121.67,128.27 | 121.67,128.27 121.67,132.08 | 121.67,132.08 121.67,135.89 119.13,138.43 119.13,157.48 116.59,157.48 | 121.67,132.08 116.59,137.16 | 116.59,137.16 116.59,134.62 | 121.67,125.73 119.13,128.27 119.13,132.08 116.59,134.62 | 124.21,125.73 121.67,125.73 | 114.05,137.16 114.05,157.48 R321.1 116.59,157.48 | 116.59,134.62 114.05,137.16 | 116.59,134.62 116.59,128.27 | 116.59,128.27 116.59,127 120.4,123.19 129.29,123.19 130.56,121.92 130.56,120.65 | 114.05,125.73 116.59,128.27 | 114.05,125.73 119.13,120.65 128.02,120.65 130.56,118.11 | 114.05,137.16 114.05,125.73 | 124.21,125.73 121.67,128.27
MASSE  (via drill 0.9 pad 1.5)
  Oben/V2 1.016: IC301.2 166.12,152.4 | G122.1 87.38,162.56 83.57,158.75 J105.2 | G322.1 102.37,162.56 106.43,158.5 J305.2 | C111.1 65.79,165.1 63.25,162.56 R122.1
  Oben/V2 1.524: 165.61,129.54 C304.2 | 131.07,129.54 C314.1 | 58.93,129.54 C114.1 | 25.15,129.54 C104.2 | 30.23,129.54 27.69,129.54 | 166.12,152.4 164.85,152.4 163.58,153.67 163.58,158.75 166.12,161.29 R311.2 | 16.26,43.18 R149.2 | 16.26,43.18 16.26,53.34 21.34,58.42 27.69,58.42 34.04,64.77 R151.1 | 16.26,43.18 16.26,41.91 17.53,40.64 R150.2 | v72.14,57.15 70.87,58.42 64.52,58.42 59.44,63.5 R175.1 | v168.66,57.15 167.39,58.42 161.04,58.42 155.96,63.5 R351.1 | 112.78,41.91 112.78,43.18 R406.1 | 112.78,41.91 112.78,53.34 117.86,58.42 124.21,58.42 130.56,64.77 R375.1 | 112.78,41.91 114.05,40.64 R399.1 | 95,182.88 v95,129.54 | 95,182.88 G120.1 91.19,184.15 91.19,186.69 | 95,182.88 G320.1 | J107.4 J107.3 J107.2 J107.5 J107.4 | J307.5 J307.2 J307.3 J307.4 J307.5
  Oben/V2 1.778: 159.26,129.54 162.31,129.54 | 136.91,129.54 134.37,129.54 | 53.09,129.54 55.63,129.54 | 35.31,156.21 C106.2 35.31,151.13 | 42.93,156.21 C109.1 42.93,151.13 | 147.07,156.21 C309.1 147.07,151.13 | 154.69,156.21 C306.2 154.69,151.13
  Oben/V2 2.159: 153.42,134.37 153.42,139.7 153.42,140.97 | 155.96,134.37 155.96,139.7 R315.2 161.04,139.7 161.04,148.59 158.5,151.13 157.23,151.13 | 162.31,129.54 165.61,129.54 | 159.26,129.54 158.5,129.54 158.5,130.3 158.25,130.56 158.25,132.08 155.96,134.37 | 134.37,129.54 131.07,129.54 | 138.18,129.54 136.91,129.54 | 153.42,134.37 153.42,135.64 | 51.82,129.54 53.09,129.54 | 55.63,129.54 58.93,129.54 | 140.72,132.08 143.01,134.37 153.42,134.37 | 153.42,134.37 154.69,134.37 155.96,134.37 | 152.15,182.88 C305.2 | 147.07,182.88 C308.1 | 37.85,185.42 C105.2 | 42.93,185.42 C108.1 | 27.69,129.54 25.15,129.54 | 31.5,129.54 30.23,129.54 | 37.85,142.24 36.58,142.24 | 36.58,142.24 35.31,140.97 | 36.58,140.97 36.58,139.7 | 36.58,139.7 36.58,135.89 | 36.58,135.89 36.58,132.08 | 36.58,140.97 35.31,140.97 | 35.31,140.97 34.04,140.97 | 34.04,140.97 34.04,139.7 | 34.04,139.7 34.04,132.08 | 35.31,140.97 35.31,132.08 | 34.04,139.7 R115.2 28.96,139.7 28.96,148.59 | 35.31,151.13 31.75,151.13 31.5,150.88 29.47,150.88 28.96,150.37 | 28.96,148.59 28.96,150.37 | 28.96,150.37 29.47,149.86 30.23,149.86 | 45.47,143.51 44.2,142.24 42.93,142.24 | 37.85,142.24 42.93,142.24 | 37.85,142.24 36.58,140.97 | 30.23,149.86 28.96,148.59 | 36.58,142.24 35.31,142.24 34.04,140.97 | G117.2 41.91,134.37 38.1,134.37 36.58,135.89 | 40.39,144.78 37.85,142.24 | 40.39,149.86 30.23,149.86 | 36.58,139.7 40.39,139.7 41.66,140.97 | 42.93,142.24 41.66,140.97 | 36.58,140.97 41.66,140.97
  Oben/V2 2.54: 154.69,139.7 155.96,139.7 | 154.69,139.7 153.42,140.97 152.15,142.24 | 154.69,134.37 154.69,139.7
  Oben/V2 2.794: C128.1 51.82,81.28 J103.2 J103.1 46.74,78.74 | G314.2 145.8,129.54 | 145.8,129.54 G313.2 | 150.88,129.54 G309.1 155.96,127 158.5,129.54 | 150.88,129.54 G308.1 | 145.8,129.54 138.18,129.54 | 143.26,127 140.72,127 138.18,129.54 | G118.2 44.2,129.54 | G117.2 44.2,129.54 | 44.2,129.54 51.82,129.54 | 51.82,129.54 49.28,127 46.74,127 G118.2 | G117.2 49.28,132.08 51.82,129.54 | 143.26,86.36 143.26,78.74 | C319.2 148.34,81.28 J301.1 143.26,78.74 | C328.1 138.18,81.28 J303.1 J303.2 143.26,78.74 | C317.2 143.26,111.76 C326.1 | 143.26,78.74 J301.2 | G313.2 140.72,132.08 138.18,129.54 | 148.34,132.08 MP5.1 150.88,129.54 | 150.88,129.54 158.5,129.54 | G308.1 155.96,132.08 158.5,129.54 | G313.2 G308.1 | 152.15,159 152.15,182.88 152.15,198.12 141.99,208.28 107.7,208.28 106.43,209.55 92.46,209.55 | 149.61,156.21 149.61,196.85 140.72,205.74 105.16,205.74 | 37.85,161.29 37.85,156.21 | 37.85,161.29 37.85,185.42 37.85,195.58 50.55,208.28 81.03,208.28 82.3,209.55 92.46,209.55 | 40.39,161.04 40.39,194.31 51.82,205.74 82.3,205.74 83.57,207.01 93.73,207.01 | 92.46,204.47 89.92,204.47 | 89.92,204.47 84.84,204.47 83.57,203.2 53.09,203.2 42.93,193.04 42.93,185.42 42.93,156.21 40.39,156.21 | 95,201.93 J2.2 | 100.08,204.47 105.16,204.47 106.43,203.2 139.45,203.2 147.07,195.58 147.07,182.88 147.07,156.21 149.61,156.21 | 100.08,204.47 97.54,204.47 | 93.73,207.01 95,207.01 | 95,207.01 95,203.2 | 95,207.01 106.43,207.01 | 93.73,207.01 92.46,208.28 92.46,209.55 | 31.5,129.54 34.04,127 G109.1 41.66,127 G118.2 | 31.5,129.54 44.2,129.54 | 31.5,129.54 34.04,132.08 35.31,132.08 36.58,132.08 G108.1 G117.2 | 37.85,151.13 35.31,151.13
  Oben/V2 2.794: 37.85,151.13 40.39,151.13 | 40.39,151.13 42.93,151.13 | 46.74,86.36 46.74,78.74 | 46.74,78.74 J101.2 | 46.74,78.74 J101.1 41.66,81.28 C119.2 | 37.85,156.21 35.31,156.21 35.31,158.75 37.85,161.29 | 149.61,156.21 152.15,156.21 | 152.15,156.21 154.69,156.21 154.69,159 152.15,159 | 152.15,156.21 152.15,159 | 147.07,151.13 149.61,151.13 | 149.61,151.13 152.15,151.13 | 153.42,151.13 152.15,151.13 | 154.69,151.13 153.42,151.13 | 149.61,151.13 149.61,156.21 | 152.15,151.13 152.15,156.21 | 154.69,151.13 157.23,151.13 | 147.07,151.13 144.53,151.13 144.53,143.51 147.07,143.51 | 147.07,143.51 147.07,151.13 | 149.61,147.32 149.61,151.13 | 149.61,146.05 149.61,147.32 | 149.61,143.51 149.61,146.05 | 149.61,143.51 147.07,143.51 | 149.61,147.32 153.42,151.13 | 149.61,146.05 154.69,151.13 | 147.07,143.51 150.37,140.21 152.91,140.21 | 153.42,139.7 152.91,140.21 | 152.91,140.21 149.61,143.51 | 37.85,156.21 40.39,156.21 | 40.39,161.04 40.39,156.21 | 40.39,161.04 40.39,161.29 | 37.85,156.21 37.85,151.13 | 40.39,156.21 40.39,151.13 | 42.93,151.13 45.47,151.13 45.47,143.51 | 42.93,151.13 42.93,143.51 | 40.39,151.13 40.39,149.86 40.39,144.78 40.39,143.51 | 92.46,195.58 J2.1 97.54,195.58 97.54,201.93 100.08,204.47 | 92.46,195.58 92.46,201.93 89.92,204.47 | 92.46,195.58 91.19,194.31 91.19,190.5
  Oben/V2 3.302: C127.1 C128.1 46.74,86.36 | C126.1 C127.1 | C327.1 C326.1 138.18,121.92 143.26,127 G314.2 | C327.1 C328.1 143.26,86.36 | C318.2 C319.2 143.26,86.36 | C318.2 C317.2 148.34,121.92 153.42,127 G309.1 | 143.26,99.06 143.26,86.36 | 143.26,99.06 143.26,111.76 v143.26,121.92 148.34,127 MP5.1 | 143.26,99.06 C318.2 | 143.26,99.06 C327.1 | 46.74,127 51.82,121.92 C126.1 | 92.46,204.47 95,201.93 97.54,204.47 | 41.66,127 v46.74,121.92 46.74,111.76 | 46.74,111.76 46.74,99.06 | 46.74,99.06 46.74,86.36 | C118.2 C119.2 46.74,86.36 | C117.2 C118.2 | G109.1 37.85,125.73 41.66,121.92 C117.2 | 46.74,111.76 C117.2 | 46.74,111.76 C126.1 | 46.74,99.06 C118.2 | 46.74,99.06 C127.1 | 95,182.88 95,184.15 93.73,184.15 91.19,186.69 91.19,190.5 91.19,191.01 95,194.82 J2.1 J2.2
  Unten/V1 1.016: 72.14,24.13 IC105.3 | IC104.3 59.44,22.86 60.71,22.86 | 163.58,137.16 166.12,139.7 | 59.44,165.1 R122.1 | 26.42,137.16 23.88,139.7 | IC101.2 18.8,154.94 | 130.56,24.13 131.83,22.86 133.1,22.86 IC304.3 | 171.2,157.48 173.74,160.02 | IC301.2 171.2,152.4 | G335.1 112.78,24.13 114.05,22.86 116.59,22.86 117.99,24.26 | C115.2 95,157.48 C315.2 | 51.82,163.07 53.85,165.1
  Unten/V1 1.524: 46.74,78.74 46.74,40.64 | R179.1 55.63,30.48 54.36,31.75 54.36,36.83 50.55,40.64 46.74,40.64 | 46.74,40.64 42.93,40.64 41.66,39.37 R161.1 C120.1 R152.2 | R172.1 MP13.1 | R172.1 MP13.1 | C121.2 IC103.2 | 46.74,40.64 R172.1 | 131.07,129.54 C314.1 | R324.1 C311.1 131.83,162.56 134.37,160.02 139.45,160.02 144.53,154.94 144.53,152.4 140.72,148.59 140.72,147.32 | 140.72,147.32 V313.1 C310.1 G313.2 | 140.72,147.32 R319.1 | 166.12,139.7 166.12,146.05 168.66,148.59 IC301.2 | 163.58,137.16 C307.2 161.04,135.89 159.77,134.62 155.96,134.62 | R311.2 C301.2 R304.2 173.74,160.02 | 165.61,129.54 C304.2 | 58.93,129.54 C114.1 | 53.85,165.1 59.44,165.1 | 23.88,139.7 IC101.2 | 26.42,137.16 C107.2 28.96,135.89 32.77,132.08 | R111.2 C101.2 R104.2 18.8,154.94 | C104.2 24.39,129.54 | G117.2 C110.1 V113.1 R118.1 49.28,151.13 51.82,153.67 51.82,163.07 | 42.93,156.21 C109.1 | C106.2 35.31,156.21 | 143.26,78.74 143.26,40.64 | R355.2 152.15,30.48 150.88,31.75 C320.1 150.88,34.29 148.34,36.83 R361.1 148.34,39.37 147.07,40.64 143.26,40.64 | 143.26,40.64 139.45,40.64 138.18,39.37 138.18,36.83 136.91,35.56 R377.1 | 125.48,15.24 125.48,20.32 | 125.48,20.32 125.48,21.59 126.75,22.86 129.29,22.86 130.56,24.13 R384.1 | 143.26,40.64 R372.1 | R372.1 MP14.1 | R359.2 155.96,12.7 153.42,12.7 | 125.48,20.32 121.92,20.32 117.99,24.26 117.86,24.38 IC305.3 | 153.42,12.7 C321.2 148.34,10.16 145.8,10.16 | 153.42,12.7 IC303.2 | J107.4 J107.3 J107.2 J107.5 84.84,2.54 82.3,5.08 45.47,5.08 44.2,6.35 R171.2 44.2,10.16 | J307.5 J307.2 J307.3 J307.4 105.16,2.54 107.7,5.08 144.53,5.08 145.8,6.35 R371.2 145.8,10.16 | 95,182.88 95,177.8 | 95,177.8 95,175.26
  Unten/V1 1.524: R115.2 34.04,139.7 | 95,175.26 95,167.64 | 95,167.64 95,162.56 | v95,129.54 95,157.48 95,162.56 | 41.66,127 MP3.1 | 148.34,127 MP5.1 | R204.2 77.22,13.97 75.95,12.7 68.33,12.7 65.79,15.24 56.9,15.24 | J101.1 36.58,76.2 36.58,68.58 R151.1 | R206.1 79.76,40.64 R199.1 70.87,40.64 69.6,41.91 69.6,54.61 v72.14,57.15 | R172.1 MP13.1 | R159.2 34.04,12.7 C121.2 | 60.71,22.86 61.98,22.86 | 61.98,22.86 67.06,22.86 | 67.06,22.86 70.87,22.86 72.14,24.13 | 95,120.14 95,119.38 | 95,119.38 97.54,116.84 101.35,116.84 102.62,118.11 J306.1 | R372.1 MP14.1 | R349.2 176.28,40.64 R350.2 167.39,40.64 166.12,41.91 166.12,54.61 v168.66,57.15 | J301.1 153.42,76.2 153.42,73.66 155.96,71.12 R351.1 | J103.2 59.44,73.66 R175.1 C129.1 | 133.1,66.04 133.1,76.2 J303.1 | 171.2,152.4 171.2,157.48 | 145.8,10.16 144.53,10.16 143.26,11.43 R372.1 | 44.2,10.16 45.47,10.16 46.74,11.43 R172.1 | 44.2,10.16 41.66,10.16 C121.2 | 56.9,15.24 IC104.3 | 95,162.56 G122.1 | 95,167.64 V117.3 | 95,177.8 V114.3 | G120.1 95,182.88 | 95,175.26 R130.2 | 95,162.56 G322.1 | 95,162.56 95,165.1 V317.3 | 95,182.88 G320.1 | 95,175.26 R330.2 | 95,177.8 V314.3 | 133.1,66.04 R375.1 | 133.1,66.04 C329.1 | 95,119.38 J106.1 | 67.06,22.86 G136.1 | MP14.1 134.37,12.7 131.83,15.24 125.48,15.24 | 125.48,15.24 R401.2 | 61.98,22.86 R183.1 | MP13.1 54.36,12.7 56.9,15.24
  Unten/V1 1.778: 136.91,129.54 134.37,129.54 | 159.77,129.54 162.31,129.54 | 30.23,129.54 27.69,129.54 | 51.82,129.54 55.63,129.54 | 147.07,154.94 C309.1 147.07,151.13 | 154.69,154.94 C306.2 154.69,151.13 | C106.2 35.31,151.13 | C109.1 42.93,151.13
